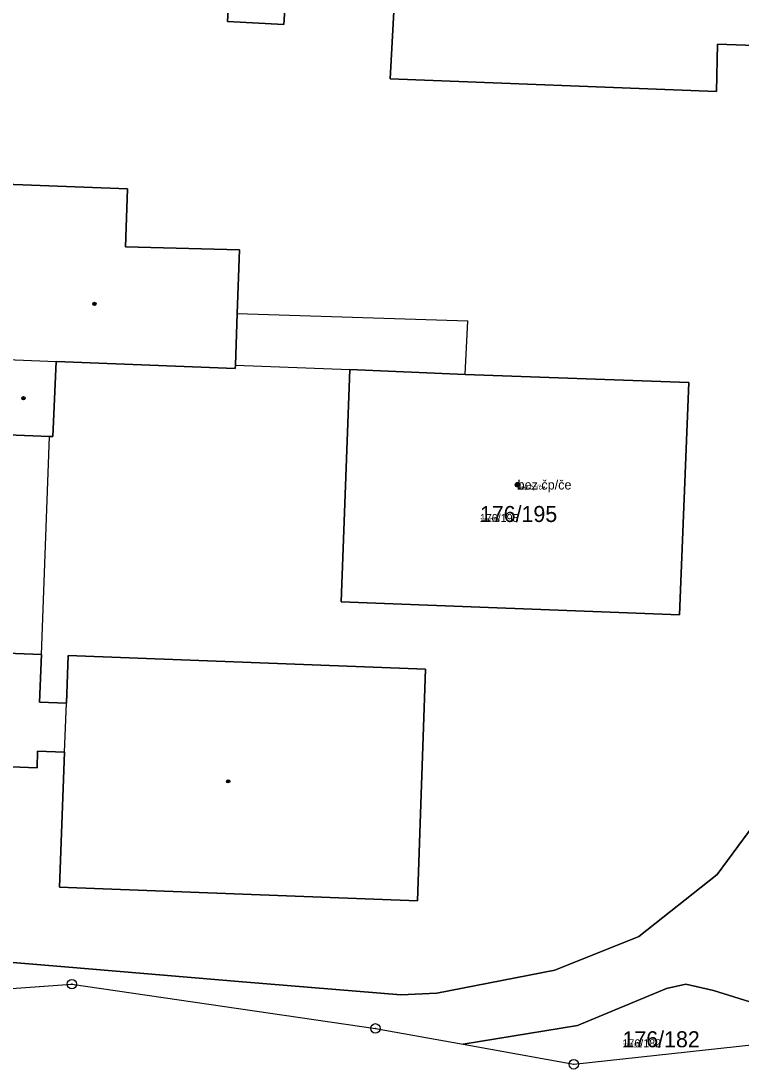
# Model space of a CAD drawing. Extents: x -759873 to -758487, y -975024 to -973516.
# Drawn here: x -759456.7 to -759380.1, y -974976.2 to -974864.9 of the extents above; entities that cross this region are included whole.
import ezdxf

# ---------------------------------------------------------------- set-up
doc = ezdxf.new("R2010")
doc.units = 0
for name, color, linetype in [('KAT_01_hranice KU', 7, 'Continuous'), ('KAT_02_hranice parcel', 7, 'Continuous'), ('KAT_03_1000_st čísla parcelní', 7, 'Continuous'), ('KAT_03_1000_čísla parcelní', 7, 'Continuous'), ('KAT_03_1000_čísla popisná', 7, 'Continuous'), ('KAT_03_250_st čísla parcelní', 7, 'Continuous'), ('KAT_03_250_čísla parcelní', 7, 'Continuous'), ('KAT_03_250_čísla popisná', 7, 'Continuous'), ('KAT_03_500_st čísla parcelní', 7, 'Continuous'), ('KAT_03_500_čísla parcelní', 7, 'Continuous'), ('KAT_03_500_čísla popisná', 7, 'Continuous'), ('KAT_04_vnitřní kresba', 7, 'Continuous'), ('KAT_07_1000_značky budov', 7, 'Continuous'), ('KAT_07_250_značky budov', 7, 'Continuous'), ('KAT_07_500_značky budov', 7, 'Continuous'), ('KAT_11_značky bodu BP', 7, 'Continuous'), ('KAT_14_plocha_budovy', 7, 'Continuous'), ('KAT_14_plocha_pozemek', 7, 'Continuous')]:
    doc.layers.add(name, color=color, linetype=linetype)

msp = doc.modelspace()

# ---------------------------------------------------------------- linework, layer by layer
at = {"layer": 'KAT_01_hranice KU'}
msp.add_lwpolyline([(-759474.45, -974968.85), (-759451.25, -974967.2), (-759419, -974971.89), (-759409.67, -974973.58), (-759397.92, -974975.71), (-759368.31, -974972.47), (-759365.9, -974972.21), (-759314.5, -974968.3), (-759297.56, -974966.67), (-759265.92, -974955.52), (-759246.78, -974946.32), (-759217.8, -974939.47), (-759196.16, -974930.91), (-759186.66, -974926.27), (-759165.4, -974915.9)], dxfattribs=at)
at = {"layer": 'KAT_02_hranice parcel'}
msp.add_line((-759474.45, -974968.85), (-759451.25, -974967.2), dxfattribs=at)
for points in [[(-759428.46, -974860.94), (-759428.73, -974865.34), (-759434.72, -974865.02), (-759434.47, -974860.67)], [(-759467.3, -974964.08), (-759451.99, -974965.37), (-759433.11, -974966.94), (-759416.3, -974968.32), (-759412.46, -974968.14), (-759399.94, -974965.73), (-759391.02, -974962.14), (-759382.69, -974955.57), (-759376.09, -974946.64), (-759370.55, -974933.42), (-759366.36, -974916.98), (-759362.58, -974902.33), (-759358.29, -974892.31), (-759352.2, -974884.34), (-759346.29, -974878.82), (-759339, -974873.54), (-759338.12, -974871.04), (-759340.2, -974868.94), (-759382.65, -974867.41), (-759382.75, -974872.45), (-759417.43, -974871.08), (-759416.91, -974861.33)], [(-759462.14, -974866.29), (-759463.26, -974894.3), (-759459.73, -974894.44), (-759459.28, -974882.23), (-759445.33, -974882.76), (-759445.56, -974888.94), (-759433.43, -974889.26), (-759433.67, -974896.02), (-759433.88, -974901.49), (-759433.89, -974901.85), (-759452.92, -974901.09), (-759453.26, -974909.07), (-759453.61, -974909.06), (-759458.99, -974908.85), (-759459.25, -974908.84), (-759459.03, -974900.84), (-759463.51, -974900.66), (-759490.49, -974899.84), (-759489.09, -974865.28), (-759462.14, -974866.29)], [(-759409.47, -974902.47), (-759385.68, -974903.32), (-759386.69, -974928.01), (-759422.64, -974926.6), (-759421.72, -974901.95), (-759409.47, -974902.47)], [(-759452.02, -974942.58), (-759454.9, -974942.47), (-759454.94, -974944.23), (-759460.45, -974944.01), (-759460.69, -974950.57), (-759498.74, -974949.16), (-759498.84, -974951.96), (-759523.42, -974951.02), (-759522.33, -974923.26), (-759497.79, -974924.21), (-759498.03, -974930.55), (-759460.02, -974931.99), (-759454.49, -974932.21), (-759454.68, -974937.27), (-759451.83, -974937.38), (-759451.64, -974932.32), (-759413.67, -974933.76), (-759414.53, -974958.36), (-759452.55, -974956.91), (-759452.02, -974942.58)], [(-759451.25, -974967.2), (-759419, -974971.89), (-759409.67, -974973.58)], [(-759370.58, -974971.76), (-759383.06, -974967.86), (-759386.03, -974967.21), (-759388.07, -974967.65), (-759397.54, -974971.59), (-759409.67, -974973.58)], [(-759409.67, -974973.58), (-759397.92, -974975.71), (-759368.31, -974972.47)]]:
    msp.add_lwpolyline(points, dxfattribs=at)
at = {"layer": 'KAT_03_1000_čísla popisná'}
msp.add_circle((-759403.89, -974914.19), 0.25, dxfattribs=at)
at = {"layer": 'KAT_03_250_čísla popisná'}
msp.add_circle((-759403.89, -974914.19), 0.0625, dxfattribs=at)
at = {"layer": 'KAT_03_500_čísla popisná'}
msp.add_circle((-759403.89, -974914.19), 0.125, dxfattribs=at)
at = {"layer": 'KAT_04_vnitřní kresba'}
for p, q in [((-759433.67, -974896.02), (-759409.18, -974896.78)), ((-759409.47, -974902.47), (-759409.18, -974896.78)), ((-759459.03, -974900.84), (-759452.92, -974901.09)), ((-759433.88, -974901.49), (-759421.72, -974901.95)), ((-759454.49, -974932.21), (-759453.61, -974909.06)), ((-759452.02, -974942.58), (-759451.83, -974937.38))]:
    msp.add_line(p, q, dxfattribs=at)
at = {"layer": 'KAT_07_1000_značky budov'}
for centre in [(-759448.85, -974894.99), (-759456.4, -974905), (-759403.9, -974914.19), (-759434.63, -974945.67)]:
    msp.add_circle(centre, 0.175, dxfattribs=at)
at = {"layer": 'KAT_07_250_značky budov'}
for centre in [(-759448.84, -974894.99), (-759456.39, -974905), (-759403.89, -974914.19), (-759434.62, -974945.67)]:
    msp.add_circle(centre, 0.0437, dxfattribs=at)
at = {"layer": 'KAT_07_500_značky budov'}
for centre in [(-759448.84, -974894.99), (-759456.39, -974905), (-759403.89, -974914.19), (-759434.62, -974945.67)]:
    msp.add_circle(centre, 0.0875, dxfattribs=at)
at = {"layer": 'KAT_11_značky bodu BP'}
for centre, radius in [((-759451.25, -974967.2), 0.5), ((-759451.25, -974967.2), 0.0303), ((-759419, -974971.89), 0.5), ((-759419, -974971.89), 0.0303), ((-759397.92, -974975.71), 0.5), ((-759397.92, -974975.71), 0.0303)]:
    msp.add_circle(centre, radius, dxfattribs=at)
at = {"layer": 'KAT_14_plocha_budovy'}
msp.add_lwpolyline([(-759386.69, -974928.01), (-759385.68, -974903.32), (-759409.47, -974902.47), (-759421.72, -974901.95), (-759422.64, -974926.6)], close=True, dxfattribs=at)
at = {"layer": 'KAT_14_plocha_pozemek'}
for points in [[(-759428.46, -974860.94), (-759428.73, -974865.34), (-759434.72, -974865.02), (-759434.47, -974860.67)], [(-759434.47, -974860.67), (-759434.72, -974865.02), (-759428.73, -974865.34), (-759428.46, -974860.94)], [(-759467.3, -974964.08), (-759451.99, -974965.37), (-759433.11, -974966.94), (-759416.3, -974968.32), (-759412.46, -974968.14), (-759399.94, -974965.73), (-759391.02, -974962.14), (-759382.69, -974955.57), (-759376.09, -974946.64), (-759370.55, -974933.42), (-759366.36, -974916.98), (-759362.58, -974902.33), (-759358.29, -974892.31), (-759352.2, -974884.34), (-759346.29, -974878.82), (-759339, -974873.54), (-759338.12, -974871.04), (-759340.2, -974868.94), (-759382.65, -974867.41), (-759382.75, -974872.45), (-759417.43, -974871.08), (-759416.91, -974861.33)], [(-759416.91, -974861.33), (-759417.43, -974871.08), (-759382.75, -974872.45), (-759382.65, -974867.41), (-759340.2, -974868.94), (-759338.12, -974871.04), (-759339, -974873.54), (-759346.29, -974878.82), (-759352.2, -974884.34), (-759358.29, -974892.31), (-759362.58, -974902.33), (-759366.36, -974916.98), (-759370.55, -974933.42), (-759376.09, -974946.64), (-759382.69, -974955.57), (-759391.02, -974962.14), (-759399.94, -974965.73), (-759412.46, -974968.14), (-759416.3, -974968.32), (-759433.11, -974966.94), (-759451.99, -974965.37), (-759467.3, -974964.08)], [(-759474.45, -974968.85), (-759451.25, -974967.2), (-759419, -974971.89), (-759409.67, -974973.58), (-759397.54, -974971.59), (-759388.07, -974967.65), (-759386.03, -974967.21), (-759383.06, -974967.86), (-759370.58, -974971.76)]]:
    msp.add_lwpolyline(points, dxfattribs=at)
for points in [[(-759462.14, -974866.29), (-759463.26, -974894.3), (-759459.73, -974894.44), (-759459.28, -974882.23), (-759445.33, -974882.76), (-759445.56, -974888.94), (-759433.43, -974889.26), (-759433.67, -974896.02), (-759433.88, -974901.49), (-759433.89, -974901.85), (-759452.92, -974901.09), (-759453.26, -974909.07), (-759453.61, -974909.06), (-759458.99, -974908.85), (-759459.25, -974908.84), (-759459.03, -974900.84), (-759463.51, -974900.66), (-759490.49, -974899.84), (-759489.09, -974865.28)], [(-759462.14, -974866.29), (-759489.09, -974865.28), (-759490.49, -974899.84), (-759463.51, -974900.66), (-759459.03, -974900.84), (-759459.25, -974908.84), (-759458.99, -974908.85), (-759453.61, -974909.06), (-759453.26, -974909.07), (-759452.92, -974901.09), (-759433.89, -974901.85), (-759433.88, -974901.49), (-759433.67, -974896.02), (-759433.43, -974889.26), (-759445.56, -974888.94), (-759445.33, -974882.76), (-759459.28, -974882.23), (-759459.73, -974894.44), (-759463.26, -974894.3)], [(-759409.47, -974902.47), (-759385.68, -974903.32), (-759386.69, -974928.01), (-759422.64, -974926.6), (-759421.72, -974901.95)], [(-759409.47, -974902.47), (-759421.72, -974901.95), (-759422.64, -974926.6), (-759386.69, -974928.01), (-759385.68, -974903.32)], [(-759452.02, -974942.58), (-759454.9, -974942.47), (-759454.94, -974944.23), (-759460.45, -974944.01), (-759460.69, -974950.57), (-759498.74, -974949.16), (-759498.84, -974951.96), (-759523.42, -974951.02), (-759522.33, -974923.26), (-759497.79, -974924.21), (-759498.03, -974930.55), (-759460.02, -974931.99), (-759454.49, -974932.21), (-759454.68, -974937.27), (-759451.83, -974937.38), (-759451.64, -974932.32), (-759413.67, -974933.76), (-759414.53, -974958.36), (-759452.55, -974956.91)], [(-759452.02, -974942.58), (-759452.55, -974956.91), (-759414.53, -974958.36), (-759413.67, -974933.76), (-759451.64, -974932.32), (-759451.83, -974937.38), (-759454.68, -974937.27), (-759454.49, -974932.21), (-759460.02, -974931.99), (-759498.03, -974930.55), (-759497.79, -974924.21), (-759522.33, -974923.26), (-759523.42, -974951.02), (-759498.84, -974951.96), (-759498.74, -974949.16), (-759460.69, -974950.57), (-759460.45, -974944.01), (-759454.94, -974944.23), (-759454.9, -974942.47)], [(-759383.06, -974967.86), (-759386.03, -974967.21), (-759388.07, -974967.65), (-759397.54, -974971.59), (-759409.67, -974973.58), (-759397.92, -974975.71), (-759368.31, -974972.47), (-759370.58, -974971.76)]]:
    msp.add_lwpolyline(points, close=True, dxfattribs=at)

# ---------------------------------------------------------------- texts
at = {"layer": 'KAT_03_1000_st čísla parcelní'}
msp.add_text('176/195', height=1.7, dxfattribs=at).set_placement((-759407.9, -974918.14))
at = {"layer": 'KAT_03_1000_čísla parcelní'}
msp.add_text('176/182', height=1.7, dxfattribs=at).set_placement((-759392.75, -974973.9))
at = {"layer": 'KAT_03_1000_čísla popisná'}
msp.add_text('bez čp/če', height=1, dxfattribs=at).set_placement((-759403.89, -974914.69))
at = {"layer": 'KAT_03_250_st čísla parcelní'}
msp.add_text('176/195', height=0.425, dxfattribs=at).set_placement((-759407.9, -974918.14))
at = {"layer": 'KAT_03_250_čísla parcelní'}
msp.add_text('176/182', height=0.425, dxfattribs=at).set_placement((-759392.75, -974973.9))
at = {"layer": 'KAT_03_250_čísla popisná'}
msp.add_text('bez čp/če', height=0.25, dxfattribs=at).set_placement((-759403.89, -974914.69))
at = {"layer": 'KAT_03_500_st čísla parcelní'}
msp.add_text('176/195', height=0.85, dxfattribs=at).set_placement((-759407.9, -974918.14))
at = {"layer": 'KAT_03_500_čísla parcelní'}
msp.add_text('176/182', height=0.85, dxfattribs=at).set_placement((-759392.75, -974973.9))
at = {"layer": 'KAT_03_500_čísla popisná'}
msp.add_text('bez čp/če', height=0.5, dxfattribs=at).set_placement((-759403.89, -974914.69))

doc.saveas('drawing.dxf')
